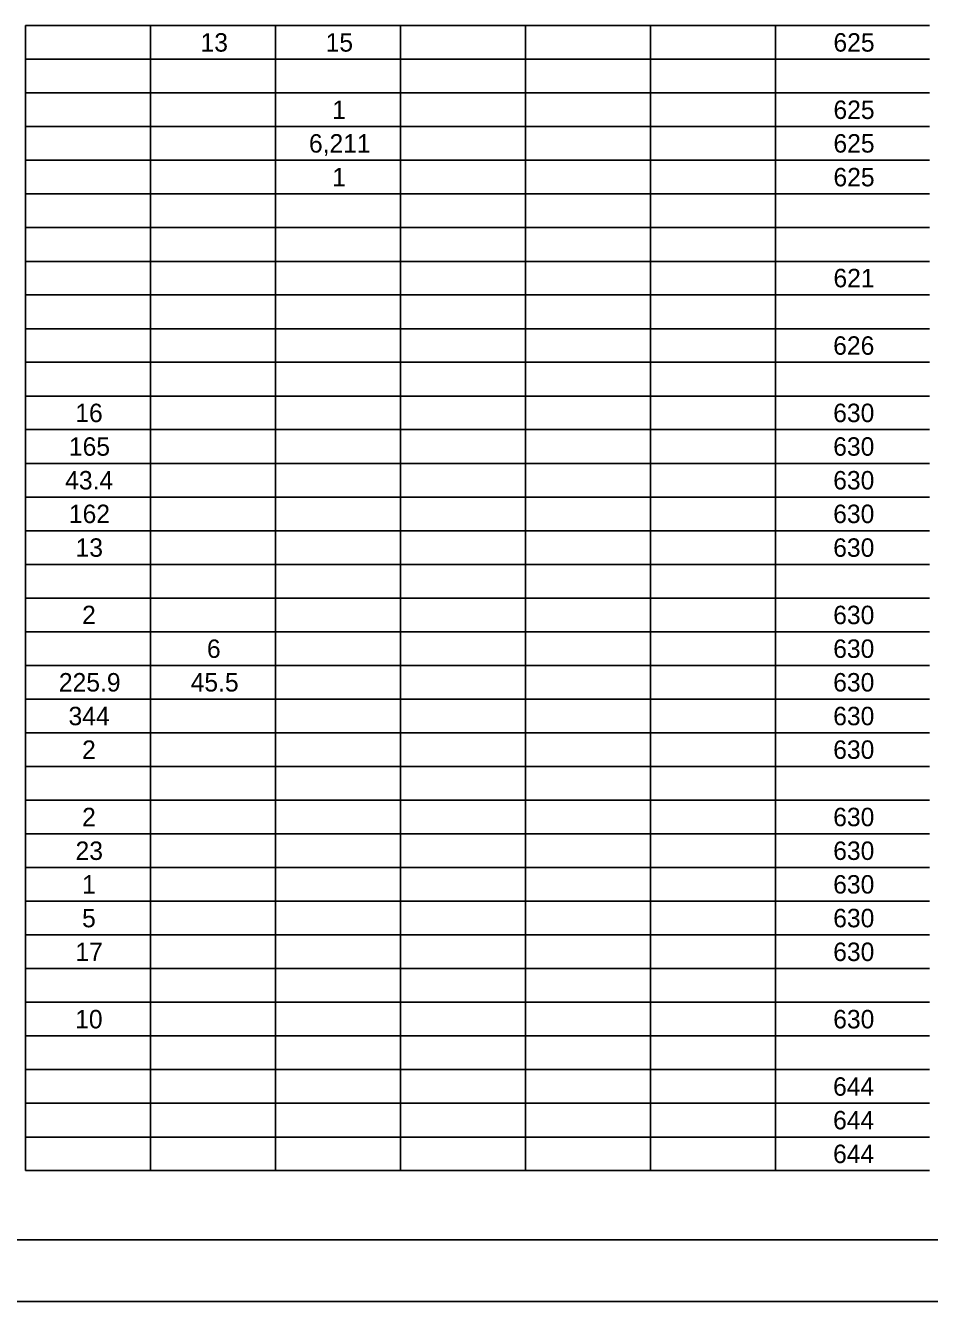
# Model space of a CAD drawing. Extents: x 0 to 34, y 0 to 22.
# Drawn here: x 9.6 to 16.92, y 0 to 10.33 of the extents above; entities that cross this region are included whole.
import ezdxf

# ---------------------------------------------------------------- set-up
doc = ezdxf.new("R2010")
doc.units = 0
for name, color, linetype in [('SH_Border', 7, 'Continuous'), ('SH_Cut_Line', 7, 'Continuous'), ('SH_Text', 7, 'Continuous')]:
    doc.layers.add(name, color=color, linetype=linetype)

msp = doc.modelspace()

# ---------------------------------------------------------------- linework, layer by layer
at = {"layer": 'SH_Border'}
msp.add_lwpolyline([(1.5, 21.5), (33.5, 21.5), (33.5, 0.5), (1.5, 0.5)], close=True, dxfattribs=at)
at = {"layer": 'SH_Cut_Line'}
msp.add_lwpolyline([(0, 0), (34, 0), (34, 22), (0, 22)], close=True, dxfattribs=at)
at = {"layer": 'SH_Text'}
for p, q in [((9.599, 10.325), (11.623, 10.325)), ((9.599, 10.325), (9.599, 10.053)), ((10.611, 10.325), (10.611, 10.053)), ((11.623, 10.325), (12.636, 10.325)), ((11.623, 10.325), (11.623, 10.053)), ((12.636, 10.325), (13.648, 10.325)), ((12.636, 10.325), (12.636, 10.053)), ((13.648, 10.325), (14.66, 10.325)), ((13.648, 10.325), (13.648, 10.053)), ((14.66, 10.325), (15.673, 10.325)), ((14.66, 10.325), (14.66, 10.053)), ((15.673, 10.325), (16.919, 10.325)), ((15.673, 10.325), (15.673, 10.053)), ((9.599, 10.053), (11.623, 10.053)), ((9.599, 10.053), (9.599, 9.235)), ((10.611, 10.053), (10.611, 9.235)), ((11.623, 10.053), (12.636, 10.053)), ((11.623, 10.053), (11.623, 9.235)), ((12.636, 10.053), (13.648, 10.053)), ((12.636, 10.053), (12.636, 9.235)), ((13.648, 10.053), (14.66, 10.053)), ((13.648, 10.053), (13.648, 9.235)), ((14.66, 10.053), (15.673, 10.053)), ((14.66, 10.053), (14.66, 9.235)), ((15.673, 10.053), (16.919, 10.053)), ((15.673, 10.053), (15.673, 9.235)), ((9.599, 9.78), (11.623, 9.78)), ((11.623, 9.78), (12.636, 9.78)), ((12.636, 9.78), (13.648, 9.78)), ((13.648, 9.78), (14.66, 9.78)), ((14.66, 9.78), (15.673, 9.78)), ((15.673, 9.78), (16.919, 9.78)), ((9.599, 9.508), (11.623, 9.508)), ((11.623, 9.508), (12.636, 9.508)), ((12.636, 9.508), (13.648, 9.508)), ((13.648, 9.508), (14.66, 9.508)), ((14.66, 9.508), (15.673, 9.508)), ((15.673, 9.508), (16.919, 9.508)), ((9.599, 9.235), (11.623, 9.235)), ((9.599, 9.235), (9.599, 8.69)), ((10.611, 9.235), (10.611, 8.69)), ((11.623, 9.235), (12.636, 9.235)), ((11.623, 9.235), (11.623, 8.69)), ((12.636, 9.235), (13.648, 9.235)), ((12.636, 9.235), (12.636, 8.69)), ((13.648, 9.235), (14.66, 9.235)), ((13.648, 9.235), (13.648, 8.69)), ((14.66, 9.235), (15.673, 9.235)), ((14.66, 9.235), (14.66, 8.69)), ((15.673, 9.235), (16.919, 9.235)), ((15.673, 9.235), (15.673, 8.69)), ((9.599, 8.963), (11.623, 8.963)), ((11.623, 8.963), (12.636, 8.963)), ((12.636, 8.963), (13.648, 8.963)), ((13.648, 8.963), (14.66, 8.963)), ((14.66, 8.963), (15.673, 8.963)), ((15.673, 8.963), (16.919, 8.963)), ((9.599, 8.69), (11.623, 8.69)), ((9.599, 8.69), (9.599, 7.872)), ((10.611, 8.69), (10.611, 7.872)), ((11.623, 8.69), (12.636, 8.69)), ((11.623, 8.69), (11.623, 7.872)), ((12.636, 8.69), (13.648, 8.69)), ((12.636, 8.69), (12.636, 7.872)), ((13.648, 8.69), (14.66, 8.69)), ((13.648, 8.69), (13.648, 7.872)), ((14.66, 8.69), (15.673, 8.69)), ((14.66, 8.69), (14.66, 7.872)), ((15.673, 8.69), (16.919, 8.69)), ((15.673, 8.69), (15.673, 7.872)), ((9.599, 8.417), (11.623, 8.417)), ((11.623, 8.417), (12.636, 8.417)), ((12.636, 8.417), (13.648, 8.417)), ((13.648, 8.417), (14.66, 8.417)), ((14.66, 8.417), (15.673, 8.417)), ((15.673, 8.417), (16.919, 8.417)), ((9.599, 8.145), (11.623, 8.145)), ((11.623, 8.145), (12.636, 8.145)), ((12.636, 8.145), (13.648, 8.145)), ((13.648, 8.145), (14.66, 8.145)), ((14.66, 8.145), (15.673, 8.145)), ((15.673, 8.145), (16.919, 8.145)), ((9.599, 7.872), (11.623, 7.872)), ((9.599, 7.872), (9.599, 7.327)), ((10.611, 7.872), (10.611, 7.327)), ((11.623, 7.872), (12.636, 7.872)), ((11.623, 7.872), (11.623, 7.327)), ((12.636, 7.872), (13.648, 7.872)), ((12.636, 7.872), (12.636, 7.327)), ((13.648, 7.872), (14.66, 7.872)), ((13.648, 7.872), (13.648, 7.327)), ((14.66, 7.872), (15.673, 7.872)), ((14.66, 7.872), (14.66, 7.327)), ((15.673, 7.872), (16.919, 7.872)), ((15.673, 7.872), (15.673, 7.327)), ((9.599, 7.6), (11.623, 7.6)), ((11.623, 7.6), (12.636, 7.6)), ((12.636, 7.6), (13.648, 7.6)), ((13.648, 7.6), (14.66, 7.6)), ((14.66, 7.6), (15.673, 7.6)), ((15.673, 7.6), (16.919, 7.6)), ((9.599, 7.327), (11.623, 7.327)), ((9.599, 7.327), (9.599, 6.51)), ((10.611, 7.327), (10.611, 6.51)), ((11.623, 7.327), (12.636, 7.327)), ((11.623, 7.327), (11.623, 6.51)), ((12.636, 7.327), (13.648, 7.327)), ((12.636, 7.327), (12.636, 6.51)), ((13.648, 7.327), (14.66, 7.327)), ((13.648, 7.327), (13.648, 6.51)), ((14.66, 7.327), (15.673, 7.327)), ((14.66, 7.327), (14.66, 6.51)), ((15.673, 7.327), (16.919, 7.327)), ((15.673, 7.327), (15.673, 6.51)), ((9.599, 7.055), (11.623, 7.055)), ((11.623, 7.055), (12.636, 7.055)), ((12.636, 7.055), (13.648, 7.055)), ((13.648, 7.055), (14.66, 7.055)), ((14.66, 7.055), (15.673, 7.055)), ((15.673, 7.055), (16.919, 7.055)), ((9.599, 6.782), (11.623, 6.782)), ((11.623, 6.782), (12.636, 6.782)), ((12.636, 6.782), (13.648, 6.782)), ((13.648, 6.782), (14.66, 6.782)), ((14.66, 6.782), (15.673, 6.782)), ((15.673, 6.782), (16.919, 6.782)), ((9.599, 6.51), (11.623, 6.51)), ((9.599, 6.51), (9.599, 5.419)), ((10.611, 6.51), (10.611, 5.419)), ((11.623, 6.51), (12.636, 6.51)), ((11.623, 6.51), (11.623, 5.419)), ((12.636, 6.51), (13.648, 6.51)), ((12.636, 6.51), (12.636, 5.419)), ((13.648, 6.51), (14.66, 6.51)), ((13.648, 6.51), (13.648, 5.419)), ((14.66, 6.51), (15.673, 6.51)), ((14.66, 6.51), (14.66, 5.419)), ((15.673, 6.51), (16.919, 6.51)), ((15.673, 6.51), (15.673, 5.419)), ((9.599, 6.237), (11.623, 6.237)), ((11.623, 6.237), (12.636, 6.237)), ((12.636, 6.237), (13.648, 6.237)), ((13.648, 6.237), (14.66, 6.237)), ((14.66, 6.237), (15.673, 6.237)), ((15.673, 6.237), (16.919, 6.237)), ((9.599, 5.964), (11.623, 5.964)), ((11.623, 5.964), (12.636, 5.964)), ((12.636, 5.964), (13.648, 5.964)), ((13.648, 5.964), (14.66, 5.964)), ((14.66, 5.964), (15.673, 5.964)), ((15.673, 5.964), (16.919, 5.964)), ((9.599, 5.692), (11.623, 5.692)), ((11.623, 5.692), (12.636, 5.692)), ((12.636, 5.692), (13.648, 5.692)), ((13.648, 5.692), (14.66, 5.692)), ((14.66, 5.692), (15.673, 5.692)), ((15.673, 5.692), (16.919, 5.692)), ((9.599, 5.419), (11.623, 5.419)), ((9.599, 5.419), (9.599, 5.147)), ((10.611, 5.419), (10.611, 5.147)), ((11.623, 5.419), (12.636, 5.419)), ((11.623, 5.419), (11.623, 5.147)), ((12.636, 5.419), (13.648, 5.419)), ((12.636, 5.419), (12.636, 5.147)), ((13.648, 5.419), (14.66, 5.419)), ((13.648, 5.419), (13.648, 5.147)), ((14.66, 5.419), (15.673, 5.419)), ((14.66, 5.419), (14.66, 5.147)), ((15.673, 5.419), (16.919, 5.419)), ((15.673, 5.419), (15.673, 5.147)), ((9.599, 5.147), (11.623, 5.147)), ((9.599, 5.147), (9.599, 4.057)), ((10.611, 5.147), (10.611, 4.057)), ((11.623, 5.147), (12.636, 5.147)), ((11.623, 5.147), (11.623, 4.057)), ((12.636, 5.147), (13.648, 5.147)), ((12.636, 5.147), (12.636, 4.057)), ((13.648, 5.147), (14.66, 5.147)), ((13.648, 5.147), (13.648, 4.057)), ((14.66, 5.147), (15.673, 5.147)), ((14.66, 5.147), (14.66, 4.057)), ((15.673, 5.147), (16.919, 5.147)), ((15.673, 5.147), (15.673, 4.057)), ((9.599, 4.874), (11.623, 4.874)), ((11.623, 4.874), (12.636, 4.874)), ((12.636, 4.874), (13.648, 4.874)), ((13.648, 4.874), (14.66, 4.874)), ((14.66, 4.874), (15.673, 4.874)), ((15.673, 4.874), (16.919, 4.874)), ((9.599, 4.602), (11.623, 4.602)), ((11.623, 4.602), (12.636, 4.602)), ((12.636, 4.602), (13.648, 4.602)), ((13.648, 4.602), (14.66, 4.602)), ((14.66, 4.602), (15.673, 4.602)), ((15.673, 4.602), (16.919, 4.602)), ((9.599, 4.329), (11.623, 4.329)), ((11.623, 4.329), (12.636, 4.329)), ((12.636, 4.329), (13.648, 4.329)), ((13.648, 4.329), (14.66, 4.329)), ((14.66, 4.329), (15.673, 4.329)), ((15.673, 4.329), (16.919, 4.329)), ((9.599, 4.057), (11.623, 4.057)), ((9.599, 4.057), (9.599, 3.784)), ((10.611, 4.057), (10.611, 3.784)), ((11.623, 4.057), (12.636, 4.057)), ((11.623, 4.057), (11.623, 3.784)), ((12.636, 4.057), (13.648, 4.057)), ((12.636, 4.057), (12.636, 3.784)), ((13.648, 4.057), (14.66, 4.057)), ((13.648, 4.057), (13.648, 3.784)), ((14.66, 4.057), (15.673, 4.057)), ((14.66, 4.057), (14.66, 3.784)), ((15.673, 4.057), (16.919, 4.057)), ((15.673, 4.057), (15.673, 3.784)), ((9.599, 3.784), (11.623, 3.784)), ((9.599, 3.784), (9.599, 2.694)), ((10.611, 3.784), (10.611, 2.694)), ((11.623, 3.784), (12.636, 3.784)), ((11.623, 3.784), (11.623, 2.694)), ((12.636, 3.784), (13.648, 3.784)), ((12.636, 3.784), (12.636, 2.694)), ((13.648, 3.784), (14.66, 3.784)), ((13.648, 3.784), (13.648, 2.694)), ((14.66, 3.784), (15.673, 3.784)), ((14.66, 3.784), (14.66, 2.694)), ((15.673, 3.784), (16.919, 3.784)), ((15.673, 3.784), (15.673, 2.694)), ((9.599, 3.511), (11.623, 3.511)), ((11.623, 3.511), (12.636, 3.511)), ((12.636, 3.511), (13.648, 3.511)), ((13.648, 3.511), (14.66, 3.511)), ((14.66, 3.511), (15.673, 3.511)), ((15.673, 3.511), (16.919, 3.511)), ((9.599, 3.239), (11.623, 3.239)), ((11.623, 3.239), (12.636, 3.239)), ((12.636, 3.239), (13.648, 3.239)), ((13.648, 3.239), (14.66, 3.239)), ((14.66, 3.239), (15.673, 3.239)), ((15.673, 3.239), (16.919, 3.239)), ((9.599, 2.966), (11.623, 2.966)), ((11.623, 2.966), (12.636, 2.966)), ((12.636, 2.966), (13.648, 2.966)), ((13.648, 2.966), (14.66, 2.966)), ((14.66, 2.966), (15.673, 2.966)), ((15.673, 2.966), (16.919, 2.966)), ((9.599, 2.694), (11.623, 2.694)), ((9.599, 2.694), (9.599, 2.421)), ((10.611, 2.694), (10.611, 2.421)), ((11.623, 2.694), (12.636, 2.694)), ((11.623, 2.694), (11.623, 2.421)), ((12.636, 2.694), (13.648, 2.694)), ((12.636, 2.694), (12.636, 2.421)), ((13.648, 2.694), (14.66, 2.694)), ((13.648, 2.694), (13.648, 2.421)), ((14.66, 2.694), (15.673, 2.694)), ((14.66, 2.694), (14.66, 2.421)), ((15.673, 2.694), (16.919, 2.694)), ((15.673, 2.694), (15.673, 2.421)), ((9.599, 2.421), (11.623, 2.421)), ((9.599, 2.421), (9.599, 1.331)), ((10.611, 2.421), (10.611, 1.331)), ((11.623, 2.421), (12.636, 2.421)), ((11.623, 2.421), (11.623, 1.331)), ((12.636, 2.421), (13.648, 2.421)), ((12.636, 2.421), (12.636, 1.331)), ((13.648, 2.421), (14.66, 2.421)), ((13.648, 2.421), (13.648, 1.331)), ((14.66, 2.421), (15.673, 2.421)), ((14.66, 2.421), (14.66, 1.331)), ((15.673, 2.421), (16.919, 2.421)), ((15.673, 2.421), (15.673, 1.331)), ((9.599, 2.149), (11.623, 2.149)), ((11.623, 2.149), (12.636, 2.149)), ((12.636, 2.149), (13.648, 2.149)), ((13.648, 2.149), (14.66, 2.149)), ((14.66, 2.149), (15.673, 2.149)), ((15.673, 2.149), (16.919, 2.149)), ((9.599, 1.876), (11.623, 1.876)), ((11.623, 1.876), (12.636, 1.876)), ((12.636, 1.876), (13.648, 1.876)), ((13.648, 1.876), (14.66, 1.876)), ((14.66, 1.876), (15.673, 1.876)), ((15.673, 1.876), (16.919, 1.876)), ((9.599, 1.604), (11.623, 1.604)), ((11.623, 1.604), (12.636, 1.604)), ((12.636, 1.604), (13.648, 1.604)), ((13.648, 1.604), (14.66, 1.604)), ((14.66, 1.604), (15.673, 1.604)), ((15.673, 1.604), (16.919, 1.604)), ((9.599, 1.331), (11.623, 1.331)), ((9.599, 1.331), (9.599, 1.059)), ((10.611, 1.331), (10.611, 1.059)), ((11.623, 1.331), (12.636, 1.331)), ((11.623, 1.331), (11.623, 1.059)), ((12.636, 1.331), (13.648, 1.331)), ((12.636, 1.331), (12.636, 1.059)), ((13.648, 1.331), (14.66, 1.331)), ((13.648, 1.331), (13.648, 1.059)), ((14.66, 1.331), (15.673, 1.331)), ((14.66, 1.331), (14.66, 1.059)), ((15.673, 1.331), (16.919, 1.331)), ((15.673, 1.331), (15.673, 1.059)), ((9.599, 1.059), (11.623, 1.059)), ((11.623, 1.059), (12.636, 1.059)), ((12.636, 1.059), (13.648, 1.059)), ((13.648, 1.059), (14.66, 1.059)), ((14.66, 1.059), (15.673, 1.059)), ((15.673, 1.059), (16.919, 1.059))]:
    msp.add_line(p, q, dxfattribs=at)

# ---------------------------------------------------------------- texts
for s, height, p in [('13', 0.1493, (11.016, 10.114)), ('15', 0.1493, (12.029, 10.114)), ('625', 0.1493, (16.141, 10.114)), ('1', 0.149, (12.082, 9.569)), ('625', 0.1493, (16.141, 9.569)), ('6,211', 0.1493, (11.894, 9.297)), ('625', 0.1493, (16.141, 9.297)), ('1', 0.149, (12.082, 9.024)), ('625', 0.1493, (16.141, 9.024)), ('621', 0.1493, (16.141, 8.207)), ('626', 0.1493, (16.139, 7.661)), ('16', 0.1493, (10.002, 7.116)), ('630', 0.1493, (16.139, 7.116)), ('165', 0.1493, (9.95, 6.844)), ('630', 0.1493, (16.139, 6.844)), ('43.4', 0.1493, (9.92, 6.571)), ('630', 0.1493, (16.139, 6.571)), ('162', 0.1493, (9.95, 6.299)), ('630', 0.1493, (16.139, 6.299)), ('13', 0.1493, (10.004, 6.026)), ('630', 0.1493, (16.139, 6.026)), ('2', 0.149, (10.057, 5.481)), ('630', 0.1493, (16.139, 5.481)), ('6', 0.149, (11.068, 5.208)), ('630', 0.1493, (16.139, 5.208)), ('225.9', 0.1493, (9.869, 4.936)), ('45.5', 0.1493, (10.936, 4.936)), ('630', 0.1493, (16.139, 4.936)), ('344', 0.1493, (9.947, 4.663)), ('630', 0.1493, (16.139, 4.663)), ('2', 0.149, (10.057, 4.391)), ('630', 0.1493, (16.139, 4.391)), ('2', 0.149, (10.057, 3.846)), ('630', 0.1493, (16.139, 3.846)), ('23', 0.1493, (10.004, 3.573)), ('630', 0.1493, (16.139, 3.573)), ('1', 0.149, (10.057, 3.301)), ('630', 0.1493, (16.139, 3.301)), ('5', 0.149, (10.057, 3.028)), ('630', 0.1493, (16.139, 3.028)), ('17', 0.1493, (10.003, 2.755)), ('630', 0.1493, (16.139, 2.755)), ('10', 0.1493, (10.001, 2.21)), ('630', 0.1493, (16.139, 2.21)), ('644', 0.1493, (16.138, 1.665)), ('644', 0.1493, (16.138, 1.393)), ('644', 0.1493, (16.138, 1.12))]:
    msp.add_text(s, height=height, dxfattribs=at).set_placement(p)

doc.saveas('drawing.dxf')
